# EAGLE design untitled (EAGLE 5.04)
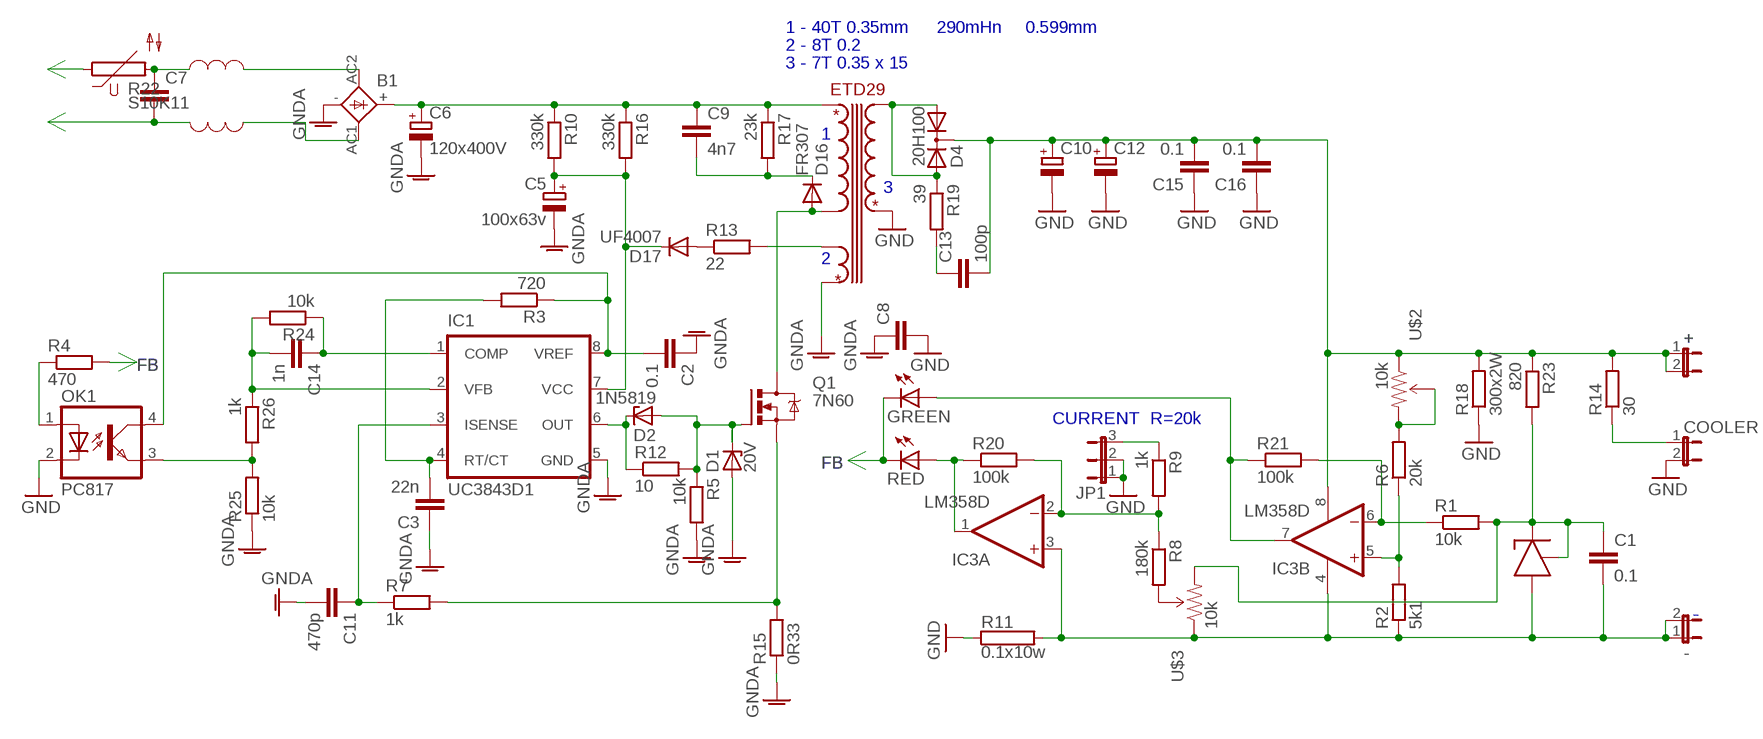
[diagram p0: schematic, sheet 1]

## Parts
+  JUMPER-2PTH  [1X02]
-  JUMPER-2PTH  [1X02]
B1  KBL  [KBL]
C1  0.1  C-EUC1206K  [C1206K]
C2  0.1  C-EUC1206K  [C1206K]
C3  22n  C-EUC1206K  [C1206K]
C5  100x63v  CPOL-EUE2.5-6  [E2,5-6]
C6  120x400V  CPOL-EUE7.5-16  [E7,5-16]
C7  C-EU102-054X133  [C102-054X133]
C8  C-EU050-030X075  [C050-030X075]
C9  4n7  C-EU050-025X075  [C050-025X075]
C10  CPOL-EUE5-13  [E5-13]
C11  470p  C-EUC1206K  [C1206K]
C12  CPOL-EUE5-13  [E5-13]
C13  100p  C-EU050-025X075  [C050-025X075]
C14  1n  C-EUC1206K  [C1206K]
C15  0.1  C-EUC1206K  [C1206K]
C16  0.1  C-EUC1206K  [C1206K]
COOLER  JUMPER-2PTH  [1X02]
D1  20V  1N4728  [DO41Z10]
D2  1N5819  1N4728  [DO41Z10]
D4  20H100  FEP16AT  [TO220ABS]
D16  FR307  1N4004  [DO41-10]
D17  UF4007  1N4004  [DO41-10]
GREEN  LED3MM  [LED3MM]
IC1  UC3843D1  [SO-08]
IC3  LM358D  [SO08]
JP1  JUMPER-3PTH  [1X03]
OK1  PC817  [DIL04]
Q1  7N60  STP5NA50  [TO220BV]
R1  10k  R-EU_0207/10  [0207/10]
R2  5k1  R-EU_0207/10  [0207/10]
R3  720  R-EU_M1206  [M1206]
R4  470  R-EU_M1206  [M1206]
R5  10k  R-EU_M1206  [M1206]
R6  20k  R-EU_0207/10  [0207/10]
R7  1k  R-EU_M1206  [M1206]
R8  180k  R-EU_0207/10  [0207/10]
R9  1k  R-EU_0207/10  [0207/10]
R10  330k  R-EU_M1206  [M1206]
R11  0.1x10w  RKH216-8  [KH216-8]
R12  10  R-EU_M1206  [M1206]
R13  22  R-EU_0411/3V  [0411V]
R14  30  R-EU_0207/10  [0207/10]
R15  0R33  R-EU_0411/3V  [0411V]
R16  330k  R-EU_M1206  [M1206]
R17  23k  R-EU_0411/3V  [0411V]
R18  300x2W  R-EU_0411/3V  [0411V]
R19  39  R-EU_0207/10  [0207/10]
R20  100k  R-EU_M1206  [M1206]
R21  100k  R-EU_M1206  [M1206]
R22  S10K11  [S10K11]
R23  820  R-EU_0207/10  [0207/10]
R24  10k  R-EU_M1206  [M1206]
R25  10k  R-EU_M1206  [M1206]
R26  1k  R-EU_M1206  [M1206]
RED  LED3MM  [LED3MM]
U$1  TL431  [TO92]
U$2  10k  TRIMPOTPTH  [TRIM_POT_PTH]
U$3  10k  TRIMPOTPTH  [TRIM_POT_PTH]
U$4  ETD29  [ETD29]

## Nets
FB: GREEN.K(C) R4.2 RED.K(C)
GND: C8.2 C10.- C12.- C15.1 C16.1 COOLER.2 JP1.1 JP1.2 OK1.2(C) R11.1 R18.1 U$4.14
GNDA: B1.- C2.1 C3.1 C5.- C6.- C8.1 C11.2 D1.A IC1.5(GND) R5.2 R15.1 R25.1 U$4.5
N$1: C14.2 IC1.2(VFB) R24.2 R26.1
N$2: C1.1 R1.2 R23.2 U$1.1(K) U$1.3(R) U$3.3(CW)
N$3: C2.2 IC1.8(VREF) OK1.4(COL) R3.1
N$4: C3.2 IC1.4(RT/CT) R3.2
N$5: R6.2 U$2.2(WIPER) U$2.3(CW)
N$6: C11.1 IC1.3(ISENSE) R7.1
N$7: IC3.6(B:-IN) R1.1 R21.2
N$8: IC3.5(B:+IN) R2.2 R6.1
N$9: +.1 +.2 C10.+ C12.+ C13.2 C15.2 C16.2 D4.C IC3.8(P:V+) R14.2 R18.2 R23.1 U$2.1(CCW)
N$10: GREEN.A IC3.7(B:OUT) R21.1
N$11: -.1 -.2 C1.2 IC3.3(A:+IN) IC3.4(P:V-) R2.1 R11.2 U$1.2(A) U$3.1(CCW)
N$12: IC3.2(A:-IN) R8.1 R9.2 R20.2
N$13: R8.2 U$3.2(WIPER)
N$14: JP1.3 R9.1
N$15: C5.+ D17.C IC1.7(VCC) R10.2 R16.2
N$16: IC3.1(A:OUT) R20.1 RED.A
N$17: COOLER.1 R14.1
N$18: OK1.1(A) R4.1
N$19: B1.+ C6.+ C9.1 R10.1 R16.1 R17.1 U$4.1 U$4.2
N$20: D2.C IC1.6(OUT) R12.1
N$21: D1.C D2.A Q1.G R5.1 R12.2
N$22: D17.A R13.1
N$23: Q1.S R7.2 R15.2
N$24: C9.2 D16.C R17.2
N$25: D4.A1 D4.A2 R19.1 U$4.8 U$4.9 U$4.10
N$26: D16.A Q1.D U$4.6 U$4.7
N$27: R13.2 U$4.3
N$29: C7.1 R22.2
N$31: C13.1 R19.2
N$34: C7.2
N$35: B1.AC2(AC1)
N$36: B1.AC1(AC2)
N$37: R22.1
N$47: C14.1 IC1.1(COMP) R24.1
N$48: OK1.3(EMIT) R25.2 R26.2
Unconnected: U$4.12 U$4.13

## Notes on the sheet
- 1 - 40T 0.35mm | 290mHn | 0.599mm
- 2 - 8T 0.2
- 3 - 7T 0.35 x 15
- 1
- 3
- 2
- +
- FB
- CURRENT | R=20k
- FB
- -

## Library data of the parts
+ - COOLER = SparkFun:JUMPER-2: Jumper
B1 = rectifier:KBL: DIOTEC RECTIFIER
C1-C3 C7-C9 C11 C13-C16 = resistor:C-EU: CAPACITOR, European symbol
C5 C6 C10 C12 = resistor:CPOL-EU: POLARIZED CAPACITOR, European symbol
D1 D2 = diode:1N4728: Z DIODE
D4 = diode:FEP16AT: DIODE dual ultra-fast recovery rectifier, common cathode
D16 D17 = diode:1N4004: DIODE
GREEN RED = led:LED: LED
IC1 = v-reg:UC384*: SMPS Controller Source: http://www.fairchildsemi.com/ds/UC/UC3843.pdf
IC3 = linear:LM358: OP AMP also LM158; LM258; LM2904 Source: http://cache.national.com/ds/LM/LM158.pdf
JP1 = SparkFun:JUMPER-3
OK1 = optocoupler:PC817: SHARP OPTO COUPLER
Q1 = transistor-power:STP5NA50: N-CHANNEL MOS FET
R1-R10 R12-R21 R23-R26 = resistor:R-EU_: RESISTOR, European symbol
R11 = resistor-power:R: Power Resitor
R22 = varistor:S10K11: VARISTOR
U$1 = transistor:TL431
U$2 U$3 = SparkFun:TRIMPOT
U$4 = trans:ETD29

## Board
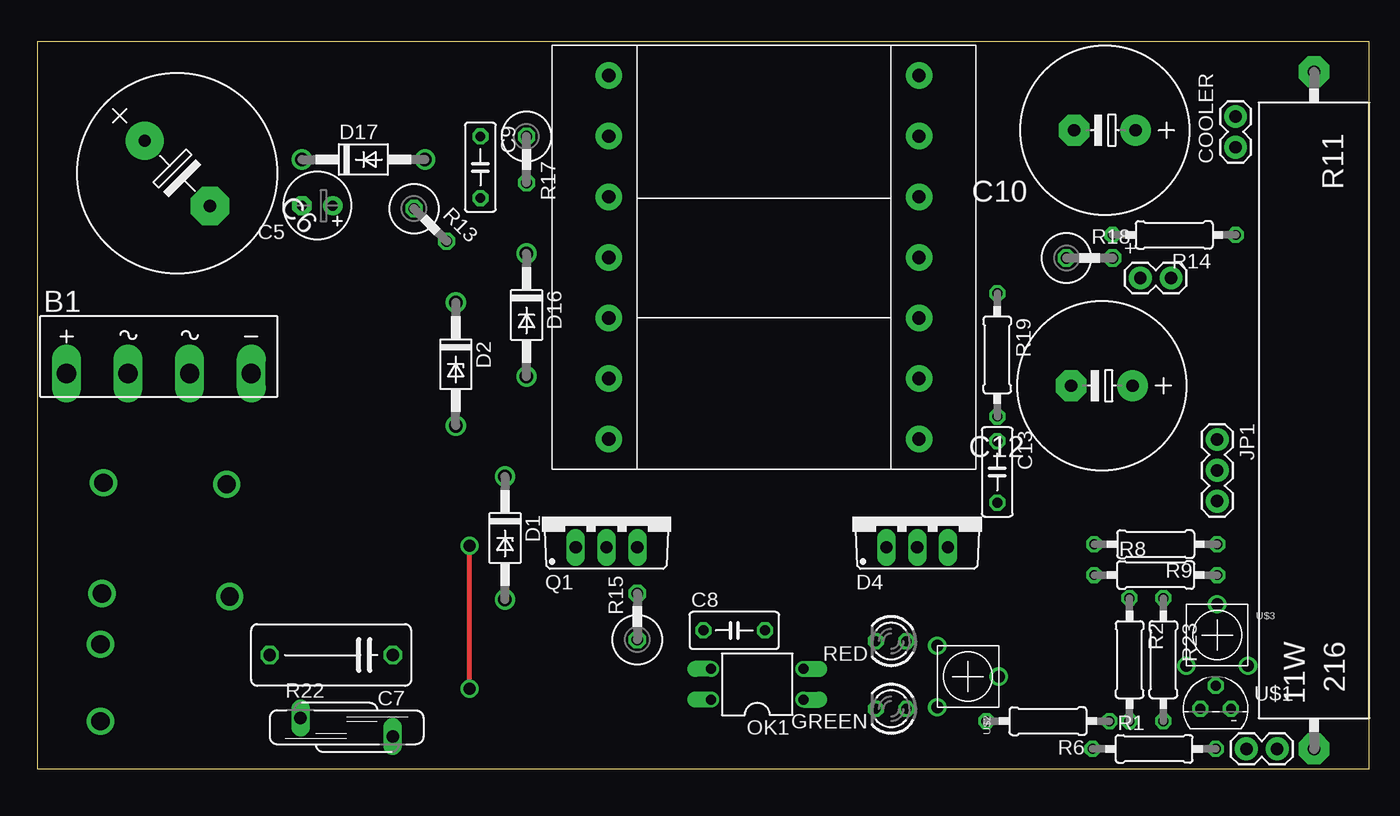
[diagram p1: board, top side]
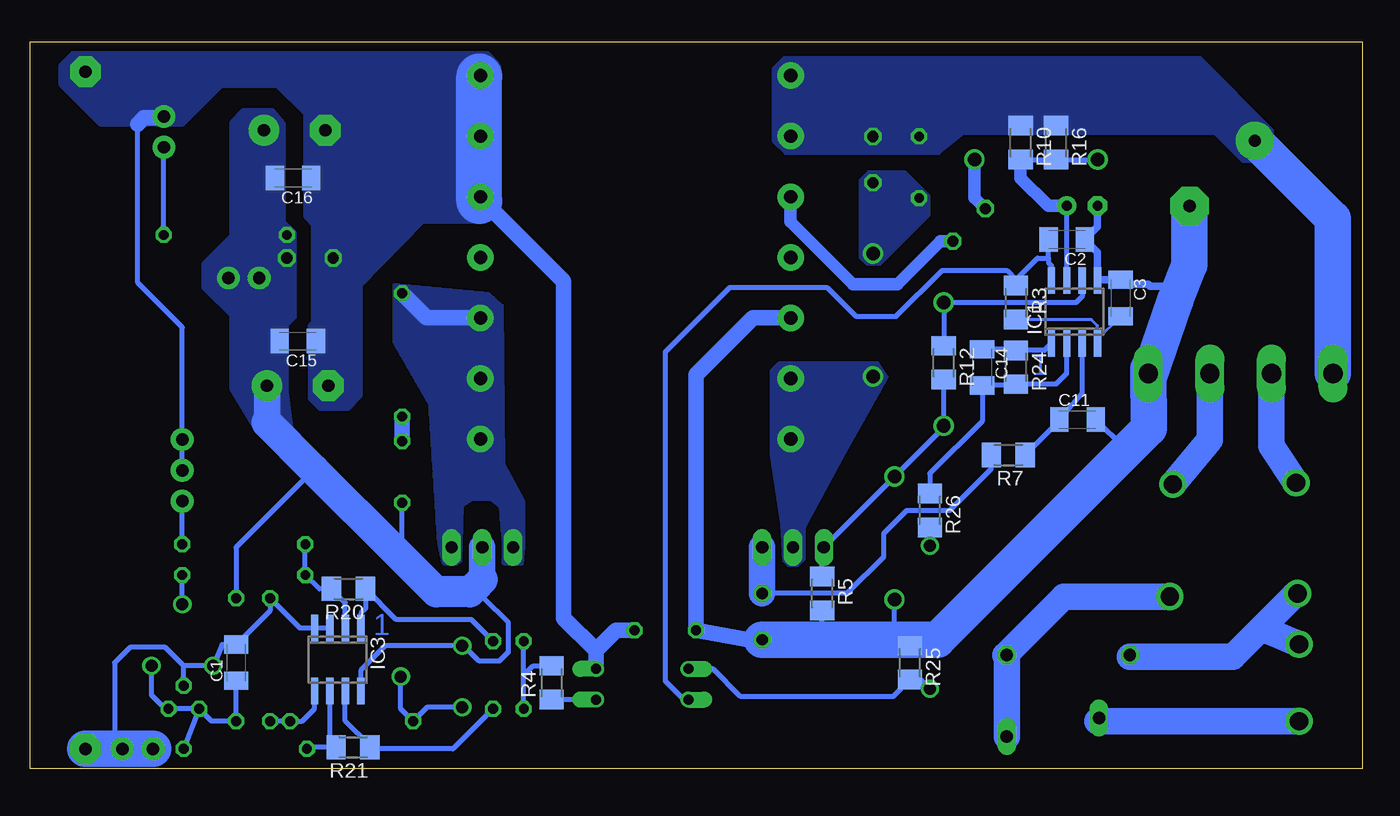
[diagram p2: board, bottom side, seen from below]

Size 109.96 x 59.99 mm. Coordinates in mm from the lower left corner, seen from the top.
Outline: 0,0 109.96,0 109.96,59.99 0,59.99 0,0
Copper layers (1*16): Top 0.035mm / dielectric 1.5mm / Bottom 0.035mm
Design rules "default": minimum track width 10mil, minimum drill 24mil, track to track 8mil, track to pad 8mil, pad to pad 8mil, via to via 8mil, smd to smd 8mil, copper to edge 0mil, drill to drill 8mil, minimum pad ring 10mil, minimum via ring 8mil, stop-mask expansion 4mil, vias tented up to drill 0mil, thermal gap 10mil

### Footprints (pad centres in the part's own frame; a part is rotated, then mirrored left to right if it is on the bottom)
1X02 = drill 1.016 pad 1.88 round: 1 0,0; 2 2.54,0
KBL = drill 1.6 long: + -7.62,-1.27; - 7.62,-1.27; AC1 2.54,-1.27; AC2 -2.54,-1.27
C1206K = smd 1.5 x 2: 1 -1.5,0; 2 1.5,0
E2,5-6 = drill 0.813 pad 1.6 round: + -1.27,0 | drill 0.813 pad 1.6 octagon: - 1.27,0
E7,5-16 = drill 1.016 pad 3.15 round: + -3.81,0 | drill 1.016 pad 3.15 octagon: - 3.81,0
C102-054X133 = drill 1.016 octagon: 1 -5.08,0; 2 5.08,0
C050-030X075 = drill 0.813 octagon: 1 -2.54,0; 2 2.54,0
C050-025X075 = drill 0.813 octagon: 1 -2.54,0; 2 2.54,0
E5-13 = drill 1.016 pad 2.54 round: + -2.54,0 | drill 1.016 pad 2.54 octagon: - 2.54,0
DO41Z10 = drill 1.118 round: A 5.08,0; C -5.08,0
TO220ABS = drill 1.016 long: A1 -2.54,-2.54; A2 2.54,-2.54; C 0,-2.54
DO41-10 = drill 1.118 round: A 5.08,0; C -5.08,0
LED3MM = drill 0.813 octagon: A -1.27,0; K 1.27,0
SO-08 = smd 0.6 x 2.2: 1 -1.905,-2.6; 2 -0.635,-2.6; 3 0.635,-2.6; 4 1.905,-2.6; 5 1.905,2.6; 6 0.635,2.6; 7 -0.635,2.6; 8 -1.905,2.6
SO08 = smd 0.6 x 2.2: 1 -1.905,-2.6; 2 -0.635,-2.6; 3 0.635,-2.6; 4 1.905,-2.6; 5 1.905,2.6; 6 0.635,2.6; 7 -0.635,2.6; 8 -1.905,2.6
1X03 = drill 1.016 pad 1.88 round: 1 0,0; 2 2.54,0; 3 5.08,0
DIL04 = drill 0.813 offset: 1 -1.27,-3.81; 2 1.27,-3.81; 3 1.27,3.81; 4 -1.27,3.81
TO220BV = drill 1.016 long: D 0,-2.54; G -2.54,-2.54; S 2.54,-2.54
0207/10 = drill 0.813 octagon: 1 -5.08,0; 2 5.08,0
M1206 = smd 1.6 x 2: 1 -1.4,0; 2 1.4,0
KH216-8 = drill 1.016 pad 2.54 octagon: 1 -27.94,0; 2 27.94,0
0411V = drill 0.914 octagon: 1 -2.54,0; 2 1.27,0
S10K11 = drill 1.016 long: 1 -0.762,-3.81; 2 0.762,3.81
TO92 = drill 0.813 octagon: 1 1.27,0; 2 0,1.905; 3 -1.27,0
TRIM_POT_PTH = drill 1 round: 1 -2.54,-2.54; 2 0,2.54; 3 2.54,-2.54
ETD29 = drill 1.1 pad 2.184 round: 1 -14.8,-12.5; 2 -9.8,-12.5; 3 -4.8,-12.5; 4 0.2,-12.5; 5 5.2,-12.5; 6 10.2,-12.5; 7 15.2,-12.5; 8 15.2,13.1; 9 10.2,13.1; 10 5.2,13.1; 11 0.2,13.1; 12 -4.8,13.1; 13 -9.8,13.1; 14 -14.8,13.1

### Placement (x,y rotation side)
+  91.06,40.51 0 top
-  99.82,1.65 0 top
B1  10.03,33.91 0 top
C1  92.96,8.76 90 bottom
C2  24.38,43.69 180 bottom
C3  19.94,38.86 270 bottom
C5  23.11,46.48 180 top
C6  11.56,49.15 315 top
C7  24.26,9.4 180 top
C8  57.53,11.43 0 top
C9  36.58,49.66 270 top
C10  88.14,52.7 180 top
C11  23.5,28.83 0 bottom
C12  87.88,31.62 180 top
C13  79.25,24.51 270 top
C14  31.37,33.15 270 bottom
C15  87.88,35.31 180 bottom
C16  88.27,48.77 180 bottom
COOLER  98.93,51.31 90 top
D1  38.61,19.05 270 top
D2  34.54,33.4 270 top
D4  72.64,20.83 0 top
D16  40.39,37.47 270 top
D17  26.92,50.29 0 top
GREEN  70.48,4.95 180 top
IC1  23.75,37.72 0 bottom
IC3  84.58,9.02 180 bottom
JP1  97.41,27.18 270 top
OK1  59.44,6.99 90 top
Q1  46.99,20.83 0 top
R1  92.2,1.65 0 top
R2  90.17,9.02 270 top
R3  28.57,38.48 270 bottom
R4  66.93,7.11 90 bottom
R5  44.58,14.48 270 bottom
R6  83.44,3.94 180 top
R7  29.21,25.91 180 bottom
R8  92.33,16 0 top
R9  92.33,18.54 180 top
R10  28.19,51.69 270 bottom
R11  105.41,29.59 270 top
R12  34.54,33.53 270 bottom
R13  32.89,44.45 315 top
R14  93.85,44.07 180 top
R15  49.53,13.21 90 top
R16  25.27,51.69 270 bottom
R17  40.39,49.66 270 top
R18  87.5,42.16 0 top
R19  79.25,34.16 270 top
R20  83.69,14.86 180 bottom
R21  83.31,1.78 180 bottom
R22  25.53,3.43 270 top
R23  92.96,9.02 270 top
R24  28.57,33.15 270 bottom
R25  37.34,8.76 270 bottom
R26  35.69,21.34 270 bottom
RED  70.48,10.54 180 top
U$1  97.28,4.95 0 top
U$2  76.83,7.62 270 top
U$3  97.41,11.05 0 top
U$4  59.69,42.42 270 top

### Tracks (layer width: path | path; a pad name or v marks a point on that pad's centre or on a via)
FB
  Bottom 0.406: GREEN.K 69.22,7.75 | 69.22,7.75 RED.K | R4.2 68.45,8.51 69.22,7.75
GND
  Bottom 0.406: JP1.2 JP1.1 97.41,36.45 101.09,40.13 101.09,53.21
  Bottom 1.27: 101.09,53.21 100.58,53.72 99.06,53.72 COOLER.2 | 72.9,46.86 72.52,46.86 65.91,40.26 65.91,12.45 63.25,9.78 | OK1.2 63.25,9.78 | C8.2 61.59,11.43 63.25,9.78 | U$4.14 72.83,57.22 72.9,57.15
  Bottom 3.81: 72.9,46.86 72.9,57.15
  pour Bottom (no thermals): 71.5,58.04 71.5,58.17 72.26,58.93 106.43,58.93 107.31,58.04 107.31,56.52 104.14,53.34 97.41,53.34 94.23,56.52 89.53,56.52 87.12,54.1 87.12,45.59 86.49,44.96 86.49,36.83 86.74,36.58 86.74,30.61 85.98,29.84 83.82,29.84 82.8,30.86 82.8,40.01 77.6,45.34 73.15,45.34 71.37,46.99 71.37,57.91
GNDA
  Bottom 0.406: 37.34,10.67 R25.1 | C11.2 19.53,26.44 19.53,26.27 17.59,28.13 | R5.2 44.58,10.79 44.7,10.67 | D1.A 38.61,10.92 38.86,10.67
  Bottom 0.61: R15.1 49.91,10.67 | C5.- 21.84,44.73 C2.1 21.84,42.65 IC1.5 21.8,40.36 C3.1 19.56,39.98 17.65,39.98 17.53,39.85 16.44,39.85 15.37,38.79
  Bottom 1.27: 47.07,37.34 U$4.5 50.28,37.22 54.99,32.51 C8.1 50.67,10.67 49.91,10.67 | B1.- 17.65,32.51 17.65,32.26
  Bottom 2.184: 17.65,33.02 17.65,32.51
  Bottom 3: 17.65,32.26 15.49,38.48 15.37,38.79 14.25,41.63 C6.- | 17.65,33.02 17.59,28.13 35.05,10.67 37.34,10.67 38.86,10.67 44.7,10.67 R15.1
N$1
  Bottom 0.406: R26.1 35.69,24.38 31.37,28.7 C14.2 28.68,31.65 R24.2 25.28,31.75 24.38,32.64 IC1.2
N$2
  Bottom 0.406: C1.1 R23.2 95,3.94 U$1.3 | U$1.3 R1.2 | U$1.3 U$1.1 98.81,4.95 99.95,6.1 U$3.3
N$3
  Bottom 0.406: 25.88,42.16 25.88,41.76 25.65,41.53 IC1.8 | 25.88,42.16 C2.2 | 28.57,40.39 R3.1 | 28.57,40.39 26.8,42.16 25.88,42.16 | OK1.4 56.01,5.71 57.53,7.24 57.53,34.42 52.2,39.75 44.2,39.75 41.78,37.34 38.48,37.34 34.67,41.15 29.34,41.15 28.57,40.39
N$4
  Bottom 0.254: C3.2 21.84,35.46 IC1.4 21.84,36.58 22.35,37.08 R3.2
N$5
  Bottom 0.406: U$2.3 77.22,5.08 R6.2 79.38,4.95 U$2.2
N$6
  Bottom 0.406: IC1.3 23.11,31.01 C11.1 25.04,28.68 R7.1
N$7
  Bottom 0.406: 85.22,1.78 85.22,1.68 | 85.22,1.78 IC3.6 | R21.2 85.22,1.78 | 85.22,1.78 87,1.78 R1.1
N$8
  Bottom 0.406: IC3.5 86.49,4.95 87.5,3.94 R6.1 R2.2
N$9
  Bottom 0.406: IC3.8 82.68,8.13 80.64,10.16 U$2.1 74.17,10.16 72.9,8.89 71.25,8.89 70.48,9.65 70.48,12.06 72.52,14.1 72.52,14.35 73.22,15.05 | C13.2 79.25,18.16 79.63,17.78 | R23.1 92.96,18.29 86.55,24.7
  Bottom 2.184: 72.64,15.62 D4.C | 73.22,15.05 73.66,14.61 | 90.42,28.57 C12.+
  Bottom 2.54: 73.22,15.05 72.64,15.62 | 73.66,14.61 76.45,14.61 79.63,17.78 86.55,24.7 90.42,28.57
  pour Bottom (no thermals): 92.33,54.23 90.04,54.23 89.15,53.21 89.15,45.09 88.27,44.2 88.27,37.34 88.9,36.7 88.9,30.99 88.52,27.81 91.06,27.81 93.22,31.37 93.22,37.47 95.5,39.75 95.5,41.66 93.22,43.94 93.22,53.34
N$10
  Bottom 0.406: GREEN.A 75.06,1.65 81.78,1.65 R21.1 81.91,1.9 83.95,3.94 IC3.7
N$11
  Bottom 0.406: IC3.3 IC3.4 87.69,11.62 R2.1 90.17,13.06 C1.2 94.13,10.26 U$3.1 97.28,8.51 | U$1.2 97.28,8.51 | 97.28,8.51 98.81,10.03 101.73,10.03 103,8.76 103,2.79 R11.2
  Bottom 3: R11.2 -.1 -.2
N$12
  Bottom 0.406: R9.2 R8.1 86.11,14.86 R20.2 83.95,13.71 IC3.2
N$13
  Bottom 0.406: U$3.2 R8.2
N$14
  Bottom 0.406: R9.1 JP1.3
N$15
  Bottom 0.406: R10.2 R16.2 22.48,50.29 D17.C | IC1.7 C5.+
  Bottom 1.016: R10.2 28.19,48.77 25.91,46.48 C5.+
N$16
  Bottom 0.406: 82.68,12.06 IC3.1 82.68,12.83 82.29,13.21 R20.1 79.76,12.32 73.53,12.32 RED.A
N$17
  Bottom 0.406: R14.1 COOLER.1
N$18
  Bottom 0.406: OK1.1 R4.1
N$19
  Bottom 3: B1.+ 2.41,45.39 C6.+
  pour Bottom (isolate 0.61, no thermals): 7.62,50.16 7.37,52.7 13.34,58.67 47.75,58.67 48.64,57.78 48.64,51.82 47.62,50.8 34.92,50.8 32.89,52.45 12.19,52.45 9.91,50.16
N$20
  Bottom 0.406: IC1.6 23.11,38.99 23.62,38.48 D2.C R12.1
N$21
  Bottom 0.406: R12.2 D2.A 34.42,28.32 D1.C Q1.G 44.58,18.16 R5.1
N$22
  Bottom 1.016: D17.A 32,47.15 R13.1
N$23
  Bottom 0.406: R15.2 42.55,14.48 39.5,17.53 39.5,19.43 37.59,21.34 34.04,21.34 30.61,24.76 R7.2
  Bottom 2.184: R15.2 Q1.S
N$24
  pour Bottom (no thermals): 35.81,47.37 35.81,45.59 39.75,41.66 40.89,41.66 41.4,42.16 41.4,48.64 40.77,49.28 37.72,49.28
N$25
  Bottom 1.27: U$4.10 77.22,37.22 R19.1
  pour Bottom (no thermals): 70.99,38.23 70.87,25.15 69.22,22.1 69.22,18.29 69.34,16.89 70.87,16.89 70.87,18.8 71.12,21.59 71.88,22.23 73.53,22.23 74.3,21.72 74.42,17.14 74.8,16.89 75.82,16.89 76.2,18.54 76.96,30.1 79.88,35.18 79.88,40.01 72.14,39.24
N$26
  pour Bottom (no thermals): 39.24,32.38 42.8,26.04 46.1,19.94 46.1,17.27 46.61,16.76 47.37,16.76 47.75,17.14 47.88,20.19 48.77,25.91 48.77,32.89 48.13,33.53 40.01,33.53
N$27
  Bottom 0.61: R13.2
  Bottom 1.016: U$4.3 47.19,45.16 42.04,40.01 38.35,40.01 34.8,43.56 R13.2
N$29
  Bottom 2.184: R22.2 C7.1
N$31
  Bottom 1.27: C13.1 R19.2
N$38  (via drill 1.5)
  Bottom 2.184: 12.57,32.77 12.57,27.18 v15.62,23.5
N$39  (via drill 1.5)
  Bottom 2.184: 7.49,32.64 7.49,26.67 v5.46,23.62
N$40  (via drill 1.5)
  other vias: 15.88,14.22
N$41  (via drill 1.5)
  other vias: 5.33,14.48
N$42
  Bottom 2.184: 15.88,14.22 24.64,14.22 29.46,9.4
N$43
  Bottom 2.184: 19.18,9.27 10.67,9.27 5.59,14.35
N$44  (via drill 1.5)
  Bottom 2.184: 21.84,3.94 v5.21,3.94 7.62,3.94
N$45  (via drill 1.5)
  other vias: 5.21,10.29
N$46
  Bottom 2.184: 5.21,10.29 7.62,11.3
N$47
  Bottom 0.406: C14.1 28.68,34.65 R24.1 26.23,34.55 IC1.1
N$48  (via drill 1)
  Top 0.406: v35.69,6.6 v35.69,18.41
  Bottom 0.406: OK1.3 53.59,8.26 51.31,5.97 38.73,5.97 R25.2 36.45,7.36 v35.69,6.6 | v35.69,18.41 R26.2

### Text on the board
Bottom: 1 | 1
